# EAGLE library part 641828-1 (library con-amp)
Universal MATE-N-LOK .250" Centerline, 600 V, 19 - 36 A max Source: http://catalog.tycoelectronics.com/ .. ENG_CD_641828_M.pdf
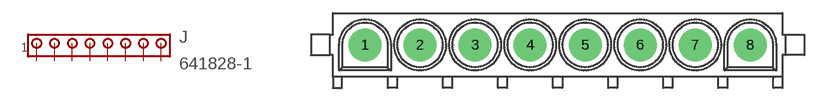
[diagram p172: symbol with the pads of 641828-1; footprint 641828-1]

Designator prefix J

## 641828-1 (MF: TYCO ELECTRONICS; MPN: 641828-1; OC_FARNELL: 4717028; OC_NEWARK: 90F4392)  [641828-1]
1  1  pas
2  2  pas
3  3  pas
4  4  pas
5  5  pas
6  6  pas
7  7  pas
8  8  pas

## Footprint 641828-1 (pad centres in mm)
Universal MATE-N-LOK .250" Centerline, 600 V, 19 - 36 A max Source: http://catalog.tycoelectronics.com/ .. ENG_CD_641828_M.pdf
drill 1.8 pad 3.81 round: 1 -22.225,0; 2 -15.875,0; 3 -9.525,0; 4 -3.175,0; 5 3.175,0; 6 9.525,0; 7 15.875,0; 8 22.225,0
